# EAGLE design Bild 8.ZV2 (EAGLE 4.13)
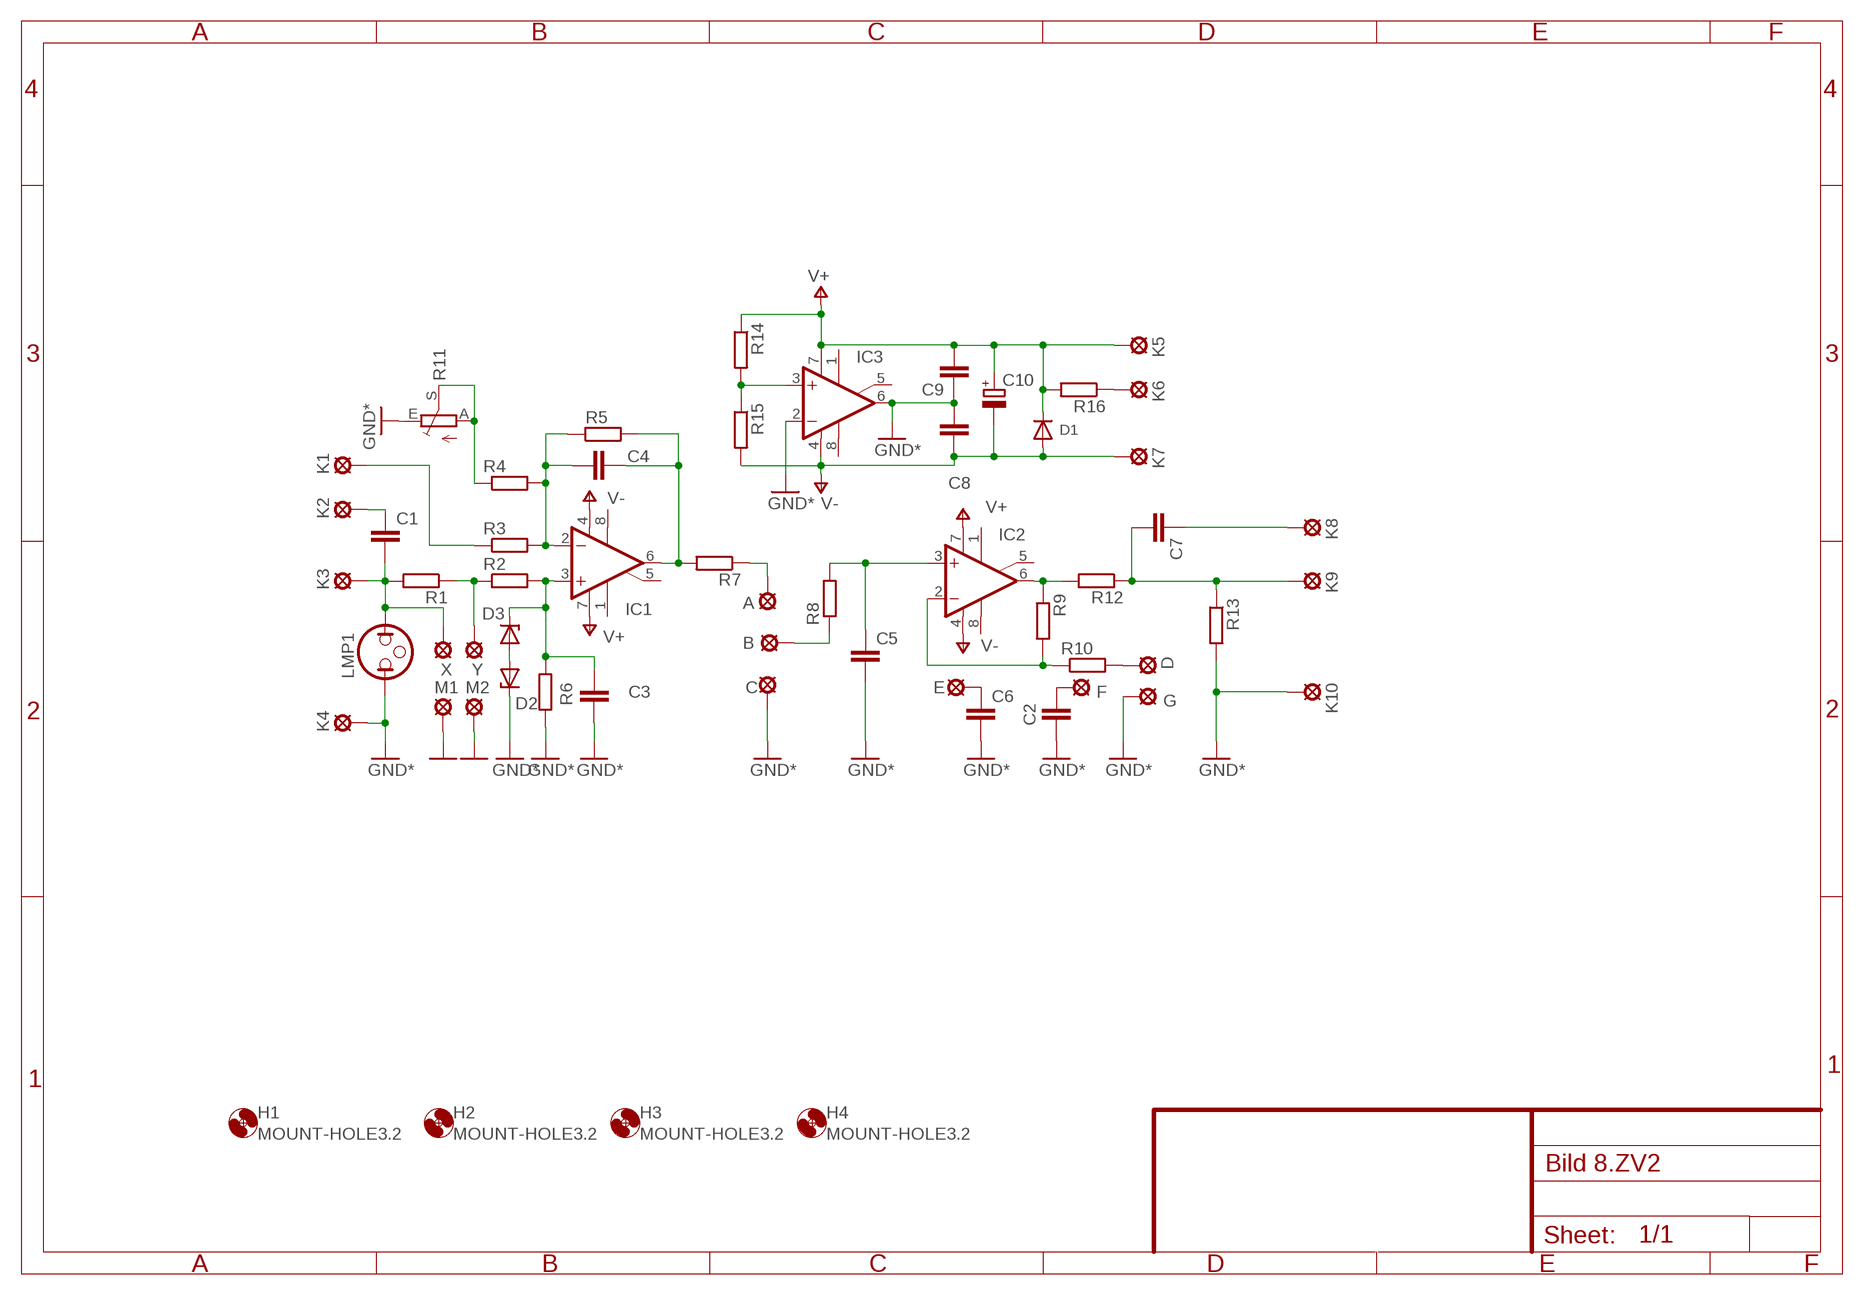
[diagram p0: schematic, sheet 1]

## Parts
A  LSP13  [LSP13]
B  LSP13  [LSP13]
C  LSP13  [LSP13]
C1  C-EU050-050X075  [C050-050X075]
C2  C-EU050-050X075  [C050-050X075]
C3  C-EU050-035X075  [C050-035X075]
C4  C-EU050-035X075  [C050-035X075]
C5  C-EU050-035X075  [C050-035X075]
C6  C-EU050-050X075  [C050-050X075]
C7  C-EU050-050X075  [C050-050X075]
C8  C-EU050-050X075  [C050-050X075]
C9  C-EU050-050X075  [C050-050X075]
C10  CPOL-EUE5-10.5  [E5-10,5]
D  LSP13  [LSP13]
D1  1N4004  [DO41-10]
D2  ZENER-DIODEDO35Z10  [DO35Z10]
D3  ZENER-DIODEDO35Z10  [DO35Z10]
E  LSP13  [LSP13]
F  LSP13  [LSP13]
G  LSP13  [LSP13]
H1  MOUNT-HOLE3.2  [3,2]
H2  MOUNT-HOLE3.2  [3,2]
H3  MOUNT-HOLE3.2  [3,2]
H4  MOUNT-HOLE3.2  [3,2]
IC1  uA741P  [DIL08]
IC2  uA741P  [DIL08]
IC3  uA741P  [DIL08]
K1  LSP13  [LSP13]
K2  LSP13  [LSP13]
K3  LSP13  [LSP13]
K4  LSP13  [LSP13]
K5  LSP13  [LSP13]
K6  LSP13  [LSP13]
K7  LSP13  [LSP13]
K8  LSP13  [LSP13]
K9  LSP13  [LSP13]
K10  LSP13  [LSP13]
LMP1  NEONGLIMM  [GLIMM]
M1  LSP13  [LSP13]
M2  LSP13  [LSP13]
R1  R-EU_0207/10E  [0207/10E]
R2  R-EU_0207/10E  [0207/10E]
R3  R-EU_0207/10E  [0207/10E]
R4  R-EU_0207/10E  [0207/10E]
R5  R-EU_0207/10E  [0207/10E]
R6  R-EU_0207/10E  [0207/10E]
R7  R-EU_0207/10E  [0207/10E]
R8  R-EU_0207/10E  [0207/10E]
R9  R-EU_0207/10E  [0207/10E]
R10  R-EU_0207/10E  [0207/10E]
R11  TRIM_EU-B64Y  [B64Y]
R12  R-EU_0207/10E  [0207/10E]
R13  R-EU_0207/10E  [0207/10E]
R14  R-EU_0207/10E  [0207/10E]
R15  R-EU_0207/10E  [0207/10E]
R16  R-EU_0207/10E  [0207/10E]
X  LSP13  [LSP13]
Y  LSP13  [LSP13]

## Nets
GND: C2.1 C3.2 C5.1 C6.1 C8.1 C9.2 C.MP D2.C G.MP IC3.2(-IN) IC3.6(OUT) K4.MP K10.MP LMP1.1 M1.MP M2.MP R6.2 R11.E R13.2 ; supply symbol labelled GND*
N$1: C4.1 IC1.2(-IN) R3.2 R4.2 R5.1
N$2: C3.1 D3.C IC1.3(+IN) R2.2 R6.1
N$3: R1.1 R2.1 Y.MP
N$4: K1.MP R3.1
N$5: C1.2 K2.MP
N$6: C1.1 K3.MP LMP1.2 R1.2 X.MP
N$7: IC2.6(OUT) R9.1 R12.2
N$8: R4.1 R11.A R11.S
N$9: C4.2 IC1.6(OUT) R5.2 R7.2
N$11: A.MP R7.1
N$12: D2.A D3.A
N$13: IC2.2(-IN) R9.2 R10.1
N$14: K6.MP R16.1
N$15: B.MP R8.1
N$16: C7.2 K8.MP
N$17: D.MP R10.2
N$18: C6.2 E.MP
N$19: C2.2 F.MP
N$20: C7.1 K9.MP R12.1 R13.1
N$21: IC3.3(+IN) R14.2 R15.1
N$22: C5.2 IC2.3(+IN) R8.2
V+: C9.1 C10.+ D1.K IC1.7(V+) IC2.7(V+) IC3.7(V+) K5.MP R14.1 R16.2
V-: C8.2 C10.- D1.A IC1.4(V-) IC2.4(V-) IC3.4(V-) K7.MP R15.2
Unconnected: IC1.1(ON1) IC1.5(ON2) IC1.8(OPT) IC2.1(ON1) IC2.5(ON2) IC2.8(OPT) IC3.1(ON1) IC3.5(ON2) IC3.8(OPT)

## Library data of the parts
A B C D E F G K1-K10 M1 M2 X Y = solpad:LSP13: SOLDER PAD
C1-C9 = rcl:C-EU: CAPACITOR, European symbol
C10 = rcl:CPOL-EU: POLARIZED CAPACITOR, European symbol
D1 = DIODE:1N4004
D2 D3 = DIODE:ZENER-DIODE: Z-Diode
H1-H4 = holes:MOUNT-HOLE: MOUNTING HOLE with drill center marker
IC1-IC3 = linear:*741P: OP AMP
LMP1 = special:NEON: Neon LAMP
R1-R10 R12-R16 = rcl:R-EU_: RESISTOR, European symbol
R11 = pot:TRIM_EU-: POTENTIOMETER

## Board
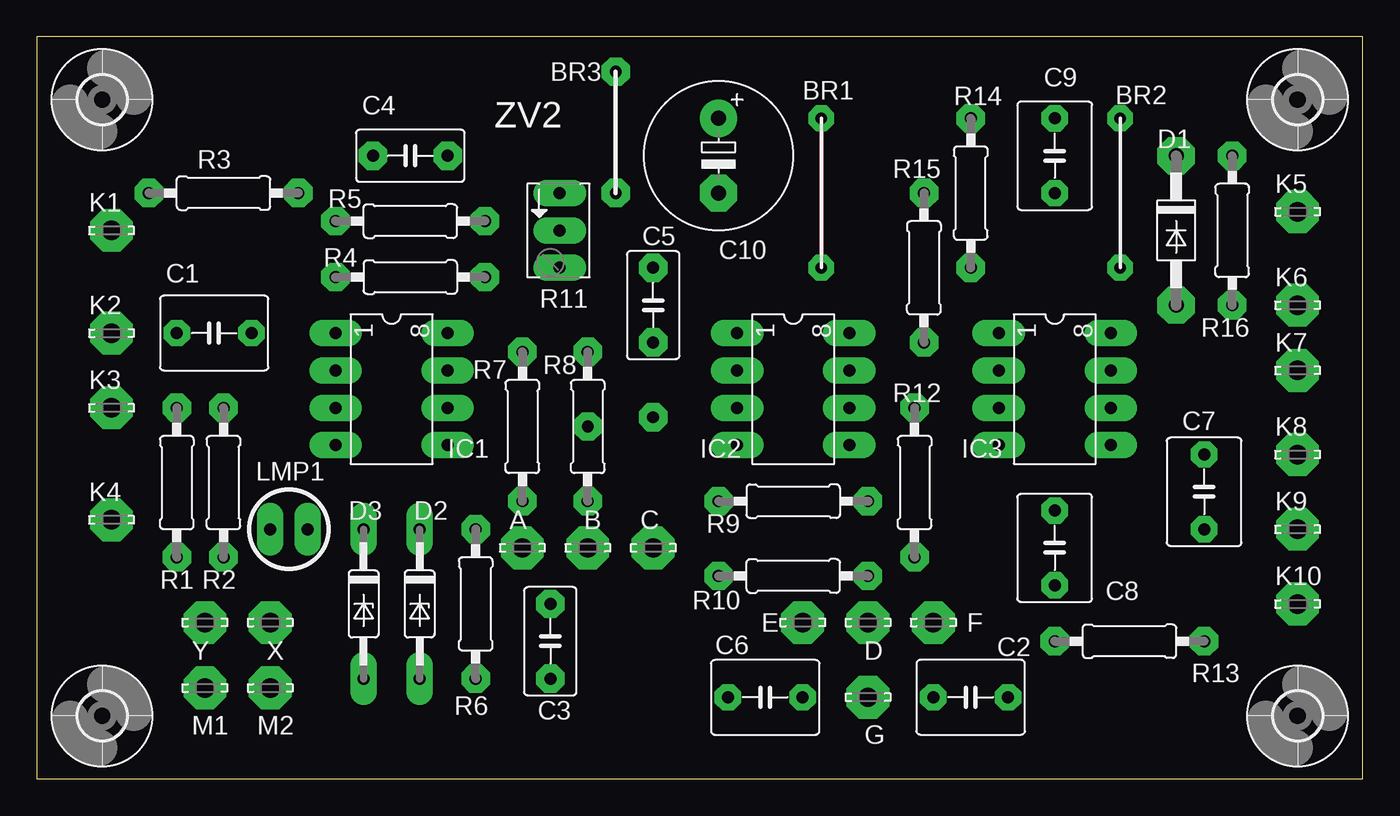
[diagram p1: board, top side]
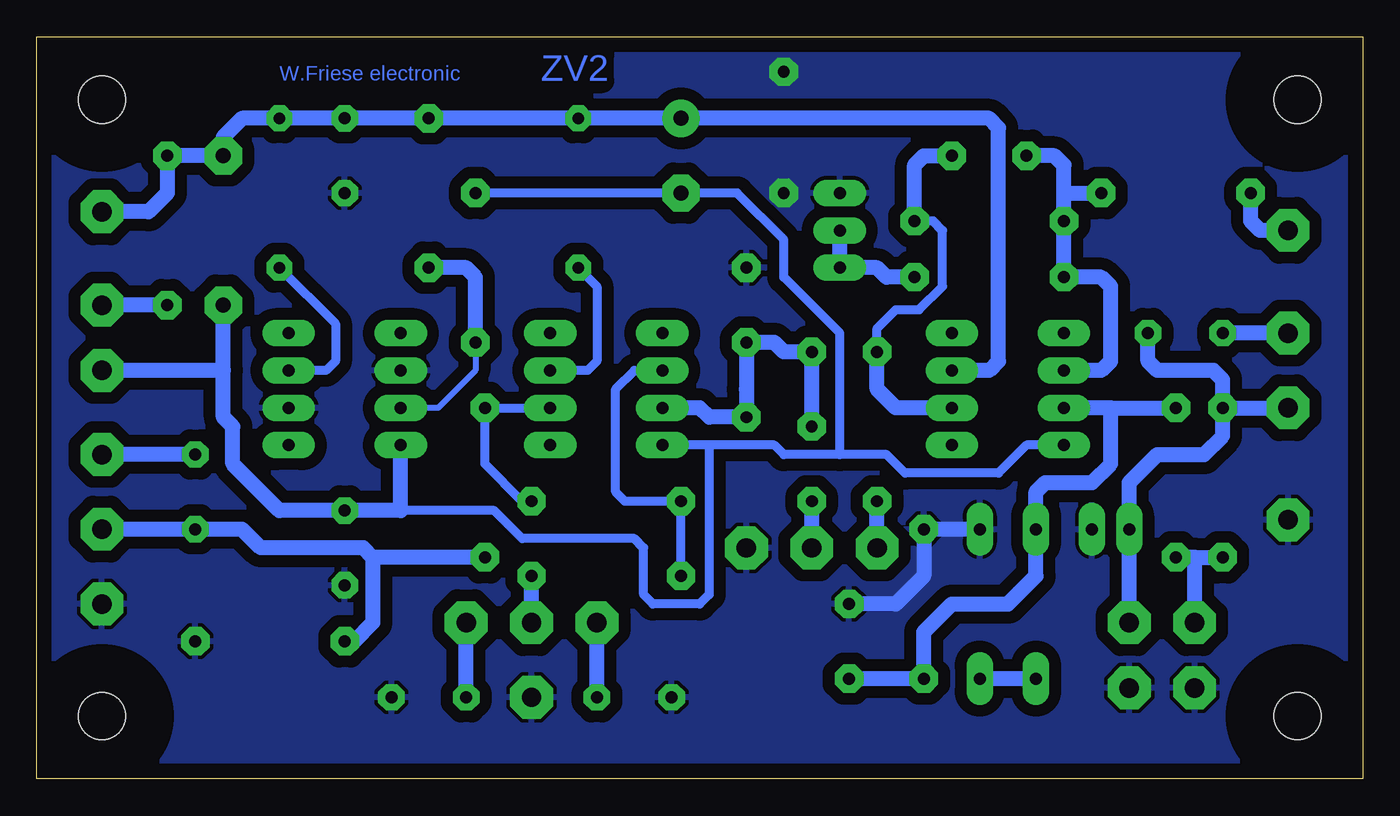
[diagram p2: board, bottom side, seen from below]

Size 90.15 x 50.47 mm. Coordinates in mm from the lower left corner, seen from the top.
Outline: 0,0 90.15,0 90.15,50.47 0,50.47 0,0
Copper layers (1*16): Top 0.035mm / dielectric 1.5mm / Bottom 0.035mm
Design rules "default": minimum track width 10mil, minimum drill 24mil, track to track 8mil, track to pad 8mil, pad to pad 8mil, via to via 8mil, smd to smd 8mil, copper to edge 40mil, drill to drill 8mil, minimum pad ring 10mil, minimum via ring 8mil, stop-mask expansion 0mil, vias tented up to drill 0mil, thermal gap 10mil

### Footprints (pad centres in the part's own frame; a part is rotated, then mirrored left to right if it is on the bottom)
LSP13 = drill 1.321 pad 2.159 octagon: MP 0,0
C050-050X075 = drill 0.813 octagon: 1 -2.54,0; 2 2.54,0
C050-035X075 = drill 0.813 pad 1.93 octagon: 1 -2.54,0; 2 2.54,0
E5-10,5 = drill 1.016 pad 2.54 round: + -2.54,0 | drill 1.016 pad 2.54 octagon: - 2.54,0
DO41-10 = drill 1.016 pad 2.54 octagon: A 5.08,0; K -5.08,0
DO35Z10 = drill 0.813 long: A 5.08,0; C -5.08,0
3,2 = hole 3.2: 0,0
DIL08 = drill 0.813 long: 1 -3.81,-3.81; 2 -1.27,-3.81; 3 1.27,-3.81; 4 3.81,-3.81; 5 3.81,3.81; 6 1.27,3.81; 7 -1.27,3.81; 8 -3.81,3.81
GLIMM = drill 0.813 long: 1 -1.27,0; 2 1.27,0
0207/10E = drill 0.813 pad 1.93 octagon: 1 -4.445,0; 2 5.715,0
B64Y = drill 0.813 long: A 2.54,0; E -2.54,0; S 0,0

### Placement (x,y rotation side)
A  33.02,15.71 0 top
B  37.46,15.71 0 top
C  41.9,15.71 0 top
C1  12.06,30.32 180 top
C2  63.49,5.55 180 top
C3  34.92,9.36 90 top
C4  25.39,42.38 0 top
C5  41.9,32.22 270 top
C6  49.52,5.55 0 top
C7  79.37,19.52 90 top
C8  69.21,15.71 90 top
C9  69.21,42.38 270 top
C10  46.35,42.38 270 top
D  56.51,10.63 0 top
D1  77.47,37.3 270 top
D2  26.03,11.9 270 top
D3  22.22,11.9 270 top
E  52.06,10.63 0 top
F  60.95,10.63 0 top
G  56.51,5.55 0 top
H1  85.72,4.28 0 top
H2  85.72,46.19 0 top
H3  4.44,4.28 0 top
H4  4.44,46.19 0 top
IC1  24.12,26.51 270 top
IC2  51.43,26.51 270 top
IC3  69.21,26.51 270 top
K1  5.08,37.3 0 top
K2  5.08,30.32 0 top
K3  5.08,25.23 0 top
K4  5.08,17.62 0 top
K5  85.72,38.57 0 top
K6  85.72,32.22 0 top
K7  85.72,27.78 0 top
K8  85.72,22.06 0 top
K9  85.72,16.98 0 top
K10  85.72,11.9 0 top
LMP1  17.14,16.98 180 top
M1  11.42,6.18 0 top
M2  15.87,6.18 0 top
R1  9.52,19.52 90 top
R2  12.69,19.52 90 top
R3  12.06,39.84 0 top
R4  26.03,34.12 180 top
R5  24.76,37.94 0 top
R6  29.84,11.27 90 top
R7  33.02,23.33 90 top
R8  37.46,23.33 90 top
R9  52.06,18.89 180 top
R10  50.79,13.81 0 top
R11  35.55,37.3 270 top
R12  59.68,19.52 90 top
R13  73.66,9.36 0 top
R14  63.49,40.48 270 top
R15  60.32,34.12 90 top
R16  81.28,36.66 90 top
X  15.87,10.63 0 top
Y  11.42,10.63 0 top

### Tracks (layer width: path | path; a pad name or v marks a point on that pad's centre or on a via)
GND  (via drill 0.8 pad 1.93)
  Bottom 1.016: C3.2 31.75,11.9 29.84,13.81 R6.2 D2.C
  other vias: 39.36,48.09 39.36,39.84
  pour Bottom (isolate 0.813): -0.01,50.63 -0.01,0.47 90.17,0.47 90.17,50.63
N$1
  Bottom 1.016: C4.1 20.95,42.38 20.32,41.74 20.32,39.84 | 20.32,39.84 R5.1 R4.2 17.78,34.12 17.14,33.49 17.14,28.41 17.78,27.78 IC1.2 | 20.32,39.84 R3.2
N$2
  Bottom 1.016: 17.14,25.23 R2.2 | 17.14,25.23 IC1.3 | C3.1 R6.1 29.84,10 27.94,11.9 24.12,11.9 22.22,13.81 D3.C 22.22,19.52 21.59,20.16 18.41,20.16 17.14,21.43 17.14,25.23
N$3
  Bottom 1.016: 11.42,15.08 R1.1 | 11.42,15.08 R2.1 | Y.MP 11.42,15.08
N$4
  Bottom 1.016: K1.MP 6.98,37.3 7.62,37.94 R3.1
N$5
  Bottom 1.016: K2.MP C1.2
N$6
  Bottom 1.016: R1.2 K3.MP | X.MP LMP1.2 15.87,20.16 13.96,22.06 10.79,22.06 9.52,23.33 R1.2 | R1.2 9.52,27.14 10.15,27.78 13.96,27.78 14.6,28.41 C1.1
N$7
  Bottom 0.61: IC2.6 R12.2 59.68,21.43 57.14,18.89 R9.1
N$8
  Bottom 1.016: R4.1 32.38,34.12 33.02,34.76 R11.A R11.S
N$9
  Bottom 0.61: R7.2 33.02,30.63 31.75,31.9 30.16,31.9 28.57,33.49 28.57,37.3 29.21,37.94 R5.2
  Bottom 1.016: IC1.6 31.75,25.23 33.02,26.51 R7.2 | C4.2 29.84,42.38 30.48,41.74 R5.2
N$11
  Bottom 1.016: A.MP R7.1
N$12
  Bottom 1.016: D3.A D2.A
N$13
  Bottom 0.61: R10.1 R9.2 50.16,18.89 50.79,19.52 50.79,26.51 49.52,27.78 IC2.2
N$14
  Bottom 1.016: R16.1 K6.MP
N$15
  Bottom 1.016: B.MP R8.1
N$16
  Bottom 1.016: C7.2 K8.MP
N$17
  Bottom 1.016: D.MP R10.2
N$18
  Bottom 1.016: C6.2 E.MP
N$19
  Bottom 1.016: C2.2 F.MP
N$20
  Bottom 1.016: R12.1 67.31,15.08 | 67.31,15.08 67.94,15.71 74.93,15.71 76.2,16.98 C7.1 K9.MP | R13.1 68.58,9.36 67.31,10.63 67.31,15.08
N$21
  Bottom 0.406: R15.1 60.32,27.78 62.86,25.23 IC3.3
  Bottom 1.016: R14.2 60.95,34.76 60.32,34.12 R15.1
N$22  (via drill 0.8 pad 1.93)
  Bottom 1.016: C5.2 40,29.68 39.36,29.05 R8.2 v37.46,23.96 | C5.2 41.9,26.51 | C5.2 v41.9,24.6 44.45,24.6 45.08,25.23 IC2.3
V+  (via drill 0.8)
  Top 0: v73.66,44.92 v73.66,34.76
  Top 0.305: v53.34,44.92 v53.34,34.76
  Bottom 0.61: v53.34,34.76 52.06,33.49 52.06,28.41 52.7,27.78 IC2.7 | IC3.7 70.48,27.78 69.84,28.41 69.84,30.95 v73.66,34.76
  Bottom 1.016: IC1.7 25.39,27.78 24.76,28.41 24.76,44.29 25.39,44.92 C10.+ v53.34,44.92 R14.1 C9.1 v73.66,44.92 76.2,44.92 77.47,43.65 D1.K R16.2 81.28,39.84 82.55,38.57 K5.MP
V-
  Bottom 0.61: IC1.4 22.86,22.7 24.76,20.79 31.11,20.79 32.38,22.06 35.55,22.06 | 35.55,22.06 39.36,22.06 40,22.7 44.45,22.7 | 44.45,22.7 IC2.4 | 65.4,18.25 59.05,18.25 57.14,16.35 49.52,16.35 48.89,15.71 48.89,12.54 48.25,11.9 45.08,11.9 44.45,12.54 44.45,22.7 | R15.2 C10.- 42.54,39.84 39.36,36.66 39.36,34.12 35.55,30.32 35.55,22.06
  Bottom 1.016: 77.47,27.78 K7.MP | 77.47,27.78 77.47,24.6 76.83,23.96 76.83,21.43 73.66,18.25 C8.2 65.4,18.25 IC3.4 | 77.47,27.78 D1.A

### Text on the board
Bottom: ZV2 | W.Friese electronic
tPlace: BR3 | BR1 | BR2 | ZV2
